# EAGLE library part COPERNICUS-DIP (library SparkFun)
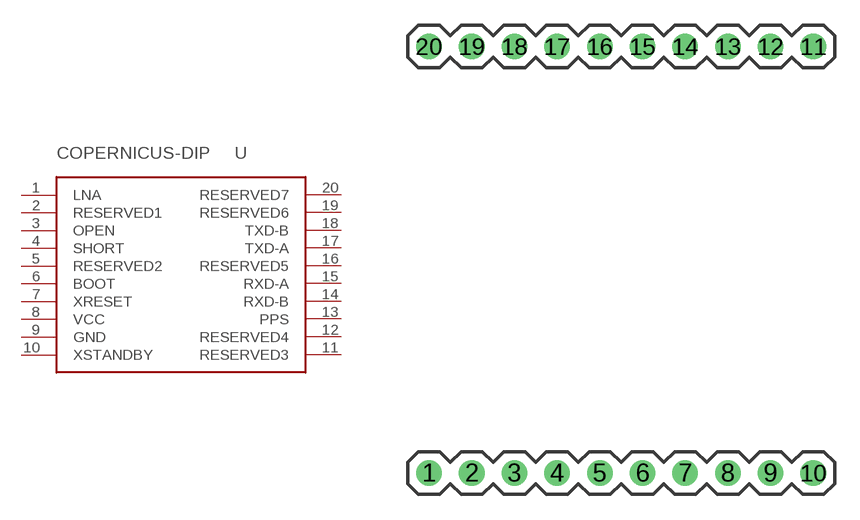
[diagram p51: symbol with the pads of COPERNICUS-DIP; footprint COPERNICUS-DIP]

Designator prefix -

## COPERNICUS-DIPPTH  [COPERNICUS-DIP]
1  LNA
2  RESERVED1
3  OPEN
4  SHORT
5  RESERVED2
6  BOOT
7  XRESET
8  VCC
9  GND
10  XSTANDBY
11  RESERVED3
12  RESERVED4
13  PPS
14  RXD-B
15  RXD-A
16  RESERVED5
17  TXD-A
18  TXD-B
19  RESERVED6
20  RESERVED7

## Footprint COPERNICUS-DIP (pad centres in mm)
drill 1.016 round: 1 0,0; 2 2.54,0; 3 5.08,0; 4 7.62,0; 5 10.16,0; 6 12.7,0; 7 15.24,0; 8 17.78,0; 9 20.32,0; 10 22.86,0; 11 22.86,25.4; 12 20.32,25.4; 13 17.78,25.4; 14 15.24,25.4; 15 12.7,25.4; 16 10.16,25.4; 17 7.62,25.4; 18 5.08,25.4; 19 2.54,25.4; 20 0,25.4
